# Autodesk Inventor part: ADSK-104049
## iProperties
Shininess: 0.0
Created: 2000-11
Part Number: ADSK-104049
Description: MECH TUBING 2-3/8" OD. x 2" ID. x 90" LONG
Document SubType Name: Modeling
Stock Number: ADSK-104049
Density: 1 g/cm^3
Density: 0.0
Volumn: 0.0
Area: 0.0
PropertySet Name: Model Information
Control State: 0
Master: False
Checked Out: False
Author: gao
